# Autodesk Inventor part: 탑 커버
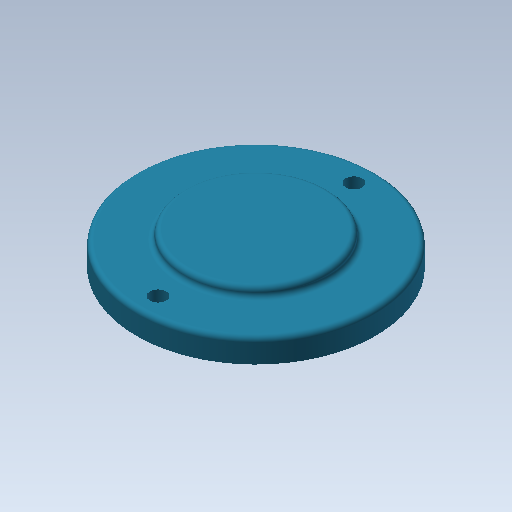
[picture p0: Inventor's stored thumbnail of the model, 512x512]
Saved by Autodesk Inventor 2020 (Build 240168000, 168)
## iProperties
Created: 2017-05
Part Number: 탑 커버
Material: 알루미늄 6061
Document SubType Name: Modeling
Designer: mduedu
Density: 1 g/cm^3
Appearance: 터키옥색
Author: mduedu
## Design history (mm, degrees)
sketch "스케치1"
  geometry: C1 r 25 at (0, 0); 1 further point
  constraints: 1 centre point, 1 coincident
  dimensions: "d31" = 50 diameter of C1
extrude "돌출1" new body sketch "스케치1" distance "d2" = 5; taper "d3" = 0 deg
sketch "스케치2"
  geometry: C1 r 15 at (0, 0); 1 further point
  constraints: 1 centre point, 1 coincident
  dimensions: "d5" = 30 diameter of C1
extrude "돌출2" join sketch "스케치2" distance "d6" = 2; taper "d7" = 0 deg
sketch "스케치3"
  geometry: C1 r 16 at (0, 0); 1 further point
  constraints: 1 centre point, 1 coincident
  dimensions: "d32" = 32 diameter of C1
extrude "돌출3" join sketch "스케치3" distance "d10" = 3; taper "d11" = 0 deg
sketch "스케치4"
  geometry: C1 r 16 at (0, 0) reference; C2 r 14 at (0, 0); 1 further point
  constraints: 1 centre point
  dimensions: "d33" = 2 radial gap between concentric circles of C2 C1
extrude "돌출4" cut sketch "스케치4" distance "d14" = 6; taper "d15" = 0 deg
chamfer "모따기1" distance "d16" = 1; stored, may be unused: second distance "d17" = 2, angle "d18" = 45 deg
fillet "모깎기3" dims "d19" = 1
fillet "모깎기4" dims "d20" = 1
fillet "모깎기5" dims "d21" = 1
sketch "스케치5" dims "d34" = 41
  geometry: C1 r 25 at (0, 0) reference; 2 further points
  constraints: 2 vertical alignment, 1 coincident, 2 other
hole "구멍2" sketch "스케치5" at (0, 20.5) diameter "d35" = 3.4; stored, may be unused: countersink angle "d39" = 90 deg, drill point angle "d41" = 118 deg; dims "d36" = 6, "d37" = 4, "d38" = 2, "d40" = 8
node "솔리드1"
pattern_circular "원형 패턴1" dims angle "d43" = 360 deg
node "투영된 루프2"
